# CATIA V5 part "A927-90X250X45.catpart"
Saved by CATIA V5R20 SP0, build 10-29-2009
Part number: A927-90X250X45
Source: Unknown
Property "A": "50.000"
Property "ARTICLENO": "A927-90X250X45"
Property "BOMINFO": "A927-90X250X45"
Property "CODE": "A927-90X250X45"
Property "CREATOR": "CADENAS GmbH"
Property "D": "18.000"
Property "D1": "26.000"
Property "F": "28.000"
Property "FORM": "A"
Property "L": "250.000"
Property "L1": "100.000"
Property "L2": "20.000"
Property "L3": "50.000"
Property "LINA": "A927-90X250X45"
Property "NB": "A927-90X250X45"
Property "NBSYN": "$CODE."
Property "NN": "A927"
Property "NT": "VDI 3387 Removable Die Heels, steel and self-lubricating"
Property "R": "25.000"
Property "S": "45.000"
Property "SUPPLIER": "CF"
Property "T": "21.000"
Property "W": "90.000"
Bounding box of the stored display mesh (mm): x -45 to 45, y 0 to 250, z -45 to 0
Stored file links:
  C:\Users\borellobunino\Desktop\3D X SITO CF\A927\GSB_OILLESS_G2290509025045\CATIAV5\A927-90X250X45.catpart
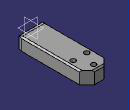
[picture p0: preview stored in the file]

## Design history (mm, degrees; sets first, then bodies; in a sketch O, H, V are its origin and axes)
Body1 "Geometry.1" (main body)
  Solid1 "A927-90X250X45.catpart": solid without history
